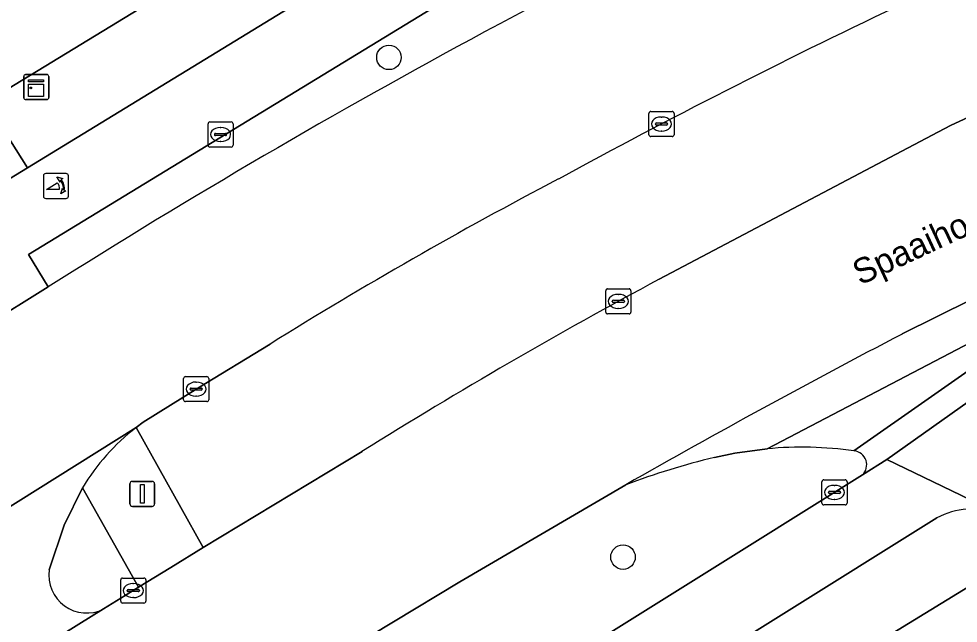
# Model space of a CAD drawing. Extents: x 157767 to 159172, y 387839 to 389425.
# Drawn here: x 158339.4 to 158376.88, y 388295.54 to 388319.67 of the extents above; entities that cross this region are included whole.
import ezdxf

# ---------------------------------------------------------------- set-up
doc = ezdxf.new("R2010")
doc.units = 0
for name, color, linetype in [('IMGEO_Berm_groen', 7, 'Continuous'), ('IMGEO_Boom', 7, 'Continuous'), ('IMGEO_Erf', 7, 'Continuous'), ('IMGEO_Fietspad_open', 7, 'Continuous'), ('IMGEO_Kast', 7, 'Continuous'), ('IMGEO_Kolk', 7, 'Continuous'), ('IMGEO_Lichtmast', 7, 'Continuous'), ('IMGEO_Openbare_ruimte_label', 7, 'Continuous'), ('IMGEO_Pand', 7, 'Continuous'), ('IMGEO_Poller', 7, 'Continuous'), ('IMGEO_Rijbaan_lokaal_gesloten', 7, 'Continuous'), ('IMGEO_Rijbaan_lokaal_open', 7, 'Continuous'), ('IMGEO_Verkeerseiland_groen', 7, 'Continuous'), ('IMGEO_Voetpad_open', 7, 'Continuous')]:
    doc.layers.add(name, color=color, linetype=linetype)

msp = doc.modelspace()

# ---------------------------------------------------------------- linework, layer by layer
at = {"layer": 'IMGEO_Berm_groen'}
for points in [[(158394.5, 388342.493), (158394.137, 388343.439), (158339.785, 388310.258), (158340.574, 388308.966)], [(158376.572, 388315.404), (158385.718, 388319.655), (158389.68, 388321.382)], [(158364.953, 388309.272), (158376.572, 388315.404)], [(158349.427, 388306.68), (158346.538, 388304.917), (158344.366, 388303.567), (158344.078, 388303.351), (158346.752, 388298.554), (158353.093, 388302.391)], [(158369.258, 388302.501), (158367.97, 388302.328), (158367.153, 388302.159)], [(158363.613, 388301.064), (158356.997, 388297.192), (158351.701, 388294), (158350.21, 388293.055), (158353.052, 388288.935), (158373.056, 388301.46)]]:
    msp.add_lwpolyline(points, dxfattribs=at)
for centre, radius, start, end in [((158493.534, 388065.053), 287.989, 113.73473, 118.07815), ((158493.159, 388070.67), 276.299, 115.45944, 118.59318), ((158499.201, 388057.708), 297.142, 118.37577, 122.26552), ((158445.272, 388152.814), 181.277, 117.72911, 121.91936), ((158462.626, 388127.262), 206.562, 118.21969, 122.02368), ((158370.643, 388287.3), 15.264, 82.1795, 95.2061), ((158372.664, 388301.862), 0.562, 17.8767, 84.2515), ((158374.95, 388270.684), 32.427, 103.9125, 110.4634), ((158372.668, 388301.862), 0.559, 314.0133, 18.055)]:
    msp.add_arc(centre, radius, start, end, dxfattribs=at)
at = {"layer": 'IMGEO_Boom'}
for centre in [(158354.168, 388318.127), (158363.505, 388298.176)]:
    msp.add_circle(centre, 0.489, dxfattribs=at)
at = {"layer": 'IMGEO_Erf'}
msp.add_lwpolyline([(158334.235, 388334.362), (158331.423, 388338.976), (158328.599, 388343.609), (158325.682, 388348.394), (158320.536, 388345.274), (158336.567, 388318.836), (158338.084, 388316.334), (158350.888, 388324.146), (158350.38, 388324.98), (158342.778, 388320.347), (158339.867, 388325.123), (158337.039, 388329.763)], close=True, dxfattribs=at)
at = {"layer": 'IMGEO_Fietspad_open'}
msp.add_lwpolyline([(158335.562, 388311.158), (158338.044, 388307.393), (158340.574, 388308.966), (158339.785, 388310.258), (158394.137, 388343.439), (158393.034, 388346.31), (158339.745, 388313.717)], close=True, dxfattribs=at)
for points in [[(158341.938, 388300.944), (158344.18, 388296.97), (158345.465, 388297.763), (158346.752, 388298.554), (158344.078, 388303.351)], [(158378.474, 388299.928), (158374.028, 388302.069), (158373.056, 388301.46), (158353.052, 388288.935), (158350.467, 388287.316), (158349.673, 388286.819), (158348.736, 388286.168), (158347.771, 388285.41), (158347, 388284.583)], [(158350.757, 388283.935), (158376.024, 388299.744)]]:
    msp.add_lwpolyline(points, dxfattribs=at)
for centre, radius, start, end in [((158349.546, 388296.335), 8.895, 127.9299, 148.7912), ((158377.455, 388297.089), 3.016, 70.2593, 118.3306)]:
    msp.add_arc(centre, radius, start, end, dxfattribs=at)
at = {"layer": 'IMGEO_Kast'}
for p, q in [((158339.672, 388317.442), (158340.513, 388317.442)), ((158340.513, 388317.442), (158339.672, 388317.442)), ((158339.597, 388316.517), (158339.597, 388317.358)), ((158339.597, 388317.358), (158339.597, 388316.517)), ((158340.597, 388317.367), (158340.597, 388316.526)), ((158340.597, 388316.526), (158340.597, 388317.367)), ((158340.522, 388316.442), (158339.681, 388316.442)), ((158339.681, 388316.442), (158340.522, 388316.442))]:
    msp.add_line(p, q, dxfattribs=at)
for points in [[(158339.792, 388317.232), (158340.392, 388317.232), (158340.392, 388317.147), (158339.792, 388317.147), (158339.792, 388317.232)], [(158339.792, 388317.057), (158340.392, 388317.057), (158340.392, 388316.568), (158339.792, 388316.568), (158339.792, 388317.057)]]:
    msp.add_lwpolyline(points, dxfattribs=at)
msp.add_circle((158339.876, 388316.906), 0.0377, dxfattribs=at)
for centre, start, end in [((158339.675, 388317.364), 92.4484, 184.2845), ((158339.675, 388317.364), 92.4484, 184.2845), ((158340.519, 388317.364), 2.4484, 94.2845), ((158340.519, 388317.364), 2.4484, 94.2845), ((158339.675, 388316.52), 182.4484, 274.2845), ((158339.675, 388316.52), 182.4484, 274.2845), ((158340.519, 388316.52), 272.4484, 4.2845), ((158340.519, 388316.52), 272.4484, 4.2845)]:
    msp.add_arc(centre, 0.0779, start, end, dxfattribs=at)
at = {"layer": 'IMGEO_Kolk'}
for p, q in [((158364.614, 388315.967), (158365.466, 388315.967)), ((158347.026, 388315.549), (158347.878, 388315.549)), ((158364.539, 388315.041), (158364.539, 388315.893)), ((158365.027, 388315.747), (158365.052, 388315.747)), ((158365.54, 388315.893), (158365.54, 388315.041)), ((158346.951, 388314.623), (158346.951, 388315.475)), ((158347.439, 388315.329), (158347.464, 388315.329)), ((158347.952, 388315.475), (158347.952, 388314.623)), ((158364.798, 388315.461), (158364.798, 388315.473)), ((158365.236, 388315.424), (158364.838, 388315.424)), ((158364.841, 388315.51), (158365.239, 388315.51)), ((158365.05, 388315.187), (158365.025, 388315.187)), ((158365.282, 388315.473), (158365.282, 388315.461)), ((158347.21, 388315.043), (158347.21, 388315.055)), ((158347.648, 388315.006), (158347.25, 388315.006)), ((158347.253, 388315.092), (158347.651, 388315.092)), ((158347.462, 388314.769), (158347.437, 388314.769)), ((158347.694, 388315.055), (158347.694, 388315.043)), ((158365.466, 388314.967), (158364.614, 388314.967)), ((158347.878, 388314.549), (158347.026, 388314.549)), ((158362.818, 388307.961), (158362.818, 388308.813)), ((158362.893, 388308.887), (158363.745, 388308.887)), ((158363.819, 388308.813), (158363.819, 388307.961)), ((158363.12, 388308.43), (158363.518, 388308.43)), ((158363.306, 388308.667), (158363.331, 388308.667)), ((158363.077, 388308.381), (158363.077, 388308.393)), ((158363.515, 388308.344), (158363.117, 388308.344)), ((158363.329, 388308.107), (158363.304, 388308.107)), ((158363.561, 388308.393), (158363.561, 388308.381)), ((158363.745, 388307.887), (158362.893, 388307.887)), ((158345.976, 388304.458), (158345.976, 388305.31)), ((158346.051, 388305.384), (158346.903, 388305.384)), ((158346.464, 388305.164), (158346.489, 388305.164)), ((158346.977, 388305.31), (158346.977, 388304.458)), ((158346.235, 388304.878), (158346.235, 388304.89)), ((158346.673, 388304.841), (158346.275, 388304.841)), ((158346.278, 388304.927), (158346.676, 388304.927)), ((158346.719, 388304.89), (158346.719, 388304.878)), ((158346.903, 388304.384), (158346.051, 388304.384)), ((158346.487, 388304.604), (158346.462, 388304.604)), ((158371.44, 388300.335), (158371.44, 388301.187)), ((158371.515, 388301.261), (158372.367, 388301.261)), ((158371.928, 388301.041), (158371.953, 388301.041)), ((158372.441, 388301.187), (158372.441, 388300.335)), ((158371.699, 388300.755), (158371.699, 388300.767)), ((158372.137, 388300.718), (158371.739, 388300.718)), ((158371.742, 388300.804), (158372.14, 388300.804)), ((158372.183, 388300.767), (158372.183, 388300.755)), ((158372.367, 388300.261), (158371.515, 388300.261)), ((158371.951, 388300.481), (158371.926, 388300.481)), ((158343.468, 388296.415), (158343.468, 388297.267)), ((158343.543, 388297.341), (158344.395, 388297.341)), ((158344.469, 388297.267), (158344.469, 388296.415)), ((158343.727, 388296.835), (158343.727, 388296.847)), ((158344.165, 388296.798), (158343.767, 388296.798)), ((158343.77, 388296.884), (158344.168, 388296.884)), ((158343.956, 388297.121), (158343.981, 388297.121)), ((158344.211, 388296.847), (158344.211, 388296.835)), ((158343.979, 388296.561), (158343.954, 388296.561)), ((158344.395, 388296.341), (158343.543, 388296.341))]:
    msp.add_line(p, q, dxfattribs=at)
for points in [[(158364.614, 388315.967), (158365.466, 388315.967)], [(158347.026, 388315.549), (158347.878, 388315.549)], [(158364.539, 388315.041), (158364.539, 388315.893)], [(158365.54, 388315.893), (158365.54, 388315.041)], [(158346.951, 388314.623), (158346.951, 388315.475)], [(158347.952, 388315.475), (158347.952, 388314.623)], [(158365.466, 388314.967), (158364.614, 388314.967)], [(158347.878, 388314.549), (158347.026, 388314.549)], [(158362.818, 388307.961), (158362.818, 388308.813)], [(158362.893, 388308.887), (158363.745, 388308.887)], [(158363.819, 388308.813), (158363.819, 388307.961)], [(158363.745, 388307.887), (158362.893, 388307.887)], [(158345.976, 388304.458), (158345.976, 388305.31)], [(158346.051, 388305.384), (158346.903, 388305.384)], [(158346.977, 388305.31), (158346.977, 388304.458)], [(158346.903, 388304.384), (158346.051, 388304.384)], [(158371.44, 388300.335), (158371.44, 388301.187)], [(158371.515, 388301.261), (158372.367, 388301.261)], [(158372.441, 388301.187), (158372.441, 388300.335)], [(158372.367, 388300.261), (158371.515, 388300.261)], [(158343.468, 388296.415), (158343.468, 388297.267)], [(158343.543, 388297.341), (158344.395, 388297.341)], [(158344.469, 388297.267), (158344.469, 388296.415)], [(158344.395, 388296.341), (158343.543, 388296.341)]]:
    msp.add_lwpolyline(points, dxfattribs=at)
for centre, radius, start, end in [((158364.616, 388315.891), 0.0765, 91.552, 178.448), ((158364.616, 388315.891), 0.0765, 91.552, 178.448), ((158365.464, 388315.891), 0.0765, 1.552, 88.448), ((158365.464, 388315.891), 0.0765, 1.552, 88.448), ((158347.028, 388315.473), 0.0765, 91.552, 178.448), ((158347.028, 388315.473), 0.0765, 91.552, 178.448), ((158347.876, 388315.473), 0.0765, 1.552, 88.448), ((158347.876, 388315.473), 0.0765, 1.552, 88.448), ((158364.838, 388315.47), 0.0403, 85.8775, 175.7526), ((158364.835, 388315.46), 0.0366, 178.938, 274.7102), ((158365.239, 388315.467), 0.043, 264.8664, 352.4533), ((158365.243, 388315.472), 0.0386, 1.7309, 96.639), ((158347.25, 388315.052), 0.0403, 85.8775, 175.7526), ((158347.247, 388315.042), 0.0366, 178.938, 274.7102), ((158347.651, 388315.049), 0.043, 264.8664, 352.4533), ((158347.655, 388315.054), 0.0386, 1.7309, 96.639), ((158364.616, 388315.043), 0.0765, 181.552, 268.448), ((158364.616, 388315.043), 0.0765, 181.552, 268.448), ((158365.464, 388315.043), 0.0765, 271.552, 358.448), ((158365.464, 388315.043), 0.0765, 271.552, 358.448), ((158347.028, 388314.625), 0.0765, 181.552, 268.448), ((158347.028, 388314.625), 0.0765, 181.552, 268.448), ((158347.876, 388314.625), 0.0765, 271.552, 358.448), ((158347.876, 388314.625), 0.0765, 271.552, 358.448), ((158362.895, 388308.811), 0.0765, 91.552, 178.448), ((158362.895, 388308.811), 0.0765, 91.552, 178.448), ((158363.743, 388308.811), 0.0765, 1.552, 88.448), ((158363.743, 388308.811), 0.0765, 1.552, 88.448), ((158363.117, 388308.39), 0.0403, 85.8775, 175.7526), ((158363.522, 388308.392), 0.0386, 1.7309, 96.639), ((158363.114, 388308.38), 0.0366, 178.938, 274.7102), ((158363.518, 388308.387), 0.043, 264.8664, 352.4533), ((158362.895, 388307.963), 0.0765, 181.552, 268.448), ((158362.895, 388307.963), 0.0765, 181.552, 268.448), ((158363.743, 388307.963), 0.0765, 271.552, 358.448), ((158363.743, 388307.963), 0.0765, 271.552, 358.448), ((158346.053, 388305.308), 0.0765, 91.552, 178.448), ((158346.053, 388305.308), 0.0765, 91.552, 178.448), ((158346.901, 388305.308), 0.0765, 1.552, 88.448), ((158346.901, 388305.308), 0.0765, 1.552, 88.448), ((158346.275, 388304.887), 0.0403, 85.8775, 175.7526), ((158346.272, 388304.877), 0.0366, 178.938, 274.7102), ((158346.676, 388304.884), 0.043, 264.8664, 352.4533), ((158346.68, 388304.889), 0.0386, 1.7309, 96.639), ((158346.053, 388304.46), 0.0765, 181.552, 268.448), ((158346.053, 388304.46), 0.0765, 181.552, 268.448), ((158346.901, 388304.46), 0.0765, 271.552, 358.448), ((158346.901, 388304.46), 0.0765, 271.552, 358.448), ((158371.517, 388301.185), 0.0765, 91.552, 178.448), ((158371.517, 388301.185), 0.0765, 91.552, 178.448), ((158372.365, 388301.185), 0.0765, 1.552, 88.448), ((158372.365, 388301.185), 0.0765, 1.552, 88.448), ((158371.739, 388300.764), 0.0403, 85.8775, 175.7526), ((158371.736, 388300.754), 0.0366, 178.938, 274.7102), ((158372.14, 388300.761), 0.043, 264.8664, 352.4533), ((158372.144, 388300.766), 0.0386, 1.7309, 96.639), ((158371.517, 388300.337), 0.0765, 181.552, 268.448), ((158371.517, 388300.337), 0.0765, 181.552, 268.448), ((158372.365, 388300.337), 0.0765, 271.552, 358.448), ((158372.365, 388300.337), 0.0765, 271.552, 358.448), ((158343.545, 388297.265), 0.0765, 91.552, 178.448), ((158343.545, 388297.265), 0.0765, 91.552, 178.448), ((158344.393, 388297.265), 0.0765, 1.552, 88.448), ((158344.393, 388297.265), 0.0765, 1.552, 88.448), ((158343.767, 388296.844), 0.0403, 85.8775, 175.7526), ((158343.764, 388296.834), 0.0366, 178.938, 274.7102), ((158344.168, 388296.841), 0.043, 264.8664, 352.4533), ((158344.172, 388296.846), 0.0386, 1.7309, 96.639), ((158343.545, 388296.417), 0.0765, 181.552, 268.448), ((158343.545, 388296.417), 0.0765, 181.552, 268.448), ((158344.393, 388296.417), 0.0765, 271.552, 358.448), ((158344.393, 388296.417), 0.0765, 271.552, 358.448)]:
    msp.add_arc(centre, radius, start, end, dxfattribs=at)
for centre, major_axis, ratio, start_param, end_param in [((158365.026, 388315.467), (-0.387, 0.002), 0.722429, 4.712389, 7.853982), ((158365.051, 388315.467), (-0.39, 0.002), 0.717154, 1.570796, 4.712389), ((158347.438, 388315.049), (-0.387, 0.002), 0.722429, 4.712389, 7.853982), ((158347.463, 388315.049), (-0.39, 0.002), 0.717154, 1.570796, 4.712389), ((158363.305, 388308.387), (-0.387, 0.002), 0.722429, 4.712389, 7.853982), ((158363.33, 388308.387), (-0.39, 0.002), 0.717154, 1.570796, 4.712389), ((158346.463, 388304.884), (-0.387, 0.002), 0.722429, 4.712389, 7.853982), ((158346.488, 388304.884), (-0.39, 0.002), 0.717154, 1.570796, 4.712389), ((158371.927, 388300.761), (-0.387, 0.002), 0.722429, 4.712389, 7.853982), ((158371.952, 388300.761), (-0.39, 0.002), 0.717154, 1.570796, 4.712389), ((158343.955, 388296.841), (-0.387, 0.002), 0.722429, 4.712389, 7.853982), ((158343.98, 388296.841), (-0.39, 0.002), 0.717154, 1.570796, 4.712389)]:
    msp.add_ellipse(centre, major_axis=major_axis, ratio=ratio, start_param=start_param, end_param=end_param, dxfattribs=at)
at = {"layer": 'IMGEO_Lichtmast'}
for p, q in [((158343.831, 388300.301), (158343.831, 388301.101)), ((158343.831, 388301.101), (158343.831, 388300.301)), ((158343.931, 388301.201), (158344.721, 388301.201)), ((158344.721, 388301.201), (158343.931, 388301.201)), ((158344.821, 388301.101), (158344.821, 388300.301)), ((158344.821, 388300.301), (158344.821, 388301.101)), ((158344.721, 388300.201), (158343.931, 388300.201)), ((158343.931, 388300.201), (158344.721, 388300.201))]:
    msp.add_line(p, q, dxfattribs=at)
msp.add_lwpolyline([(158344.251, 388301.076), (158344.401, 388301.076), (158344.401, 388300.326), (158344.251, 388300.326), (158344.251, 388301.076)], dxfattribs=at)
for centre, start, end in [((158343.931, 388301.101), 90, 180), ((158343.931, 388301.101), 90, 180), ((158344.721, 388301.101), 0, 90), ((158344.721, 388301.101), 360, 90), ((158343.931, 388300.301), 180, 270), ((158343.931, 388300.301), 180, 270), ((158344.721, 388300.301), 270, 0), ((158344.721, 388300.301), 270, 0)]:
    msp.add_arc(centre, 0.1, start, end, dxfattribs=at)
at = {"layer": 'IMGEO_Pand'}
msp.add_lwpolyline([(158378.945, 388290.243), (158381.202, 388291.668), (158379.006, 388295.224), (158377.739, 388297.275), (158374.241, 388295.13), (158377.725, 388289.49)], close=True, dxfattribs=at)
at = {"layer": 'IMGEO_Poller'}
for p, q in [((158340.383, 388313.397), (158340.383, 388312.59)), ((158340.383, 388313.397), (158340.383, 388312.59)), ((158341.285, 388313.492), (158340.477, 388313.492)), ((158341.285, 388313.492), (158340.477, 388313.492)), ((158341.379, 388312.59), (158341.379, 388313.397)), ((158341.379, 388312.59), (158341.379, 388313.397)), ((158340.477, 388312.495), (158341.285, 388312.495)), ((158340.477, 388312.495), (158341.285, 388312.495))]:
    msp.add_line(p, q, dxfattribs=at)
for points in [[(158341.062, 388313.221), (158341.05, 388313.148), (158340.925, 388313.353)], [(158340.925, 388313.353), (158341.156, 388313.287), (158341.085, 388313.255)], [(158341.018, 388312.848), (158340.505, 388312.848), (158340.935, 388313.123)], [(158341.078, 388312.676), (158341.144, 388312.907), (158341.174, 388312.839)], [(158341.21, 388312.812), (158341.282, 388312.801), (158341.078, 388312.676)]]:
    msp.add_lwpolyline(points, dxfattribs=at)
for centre, radius, start, end in [((158340.477, 388313.397), 0.0946, 90, 180), ((158340.477, 388313.397), 0.0946, 90, 180), ((158341.285, 388313.397), 0.0946, 0, 90), ((158341.285, 388313.397), 0.0946, 0, 90), ((158340.69, 388312.898), 0.332, 351.3247, 42.4854), ((158340.704, 388312.908), 0.476, 351.7527, 41.1691), ((158340.704, 388312.908), 0.516, 349.3569, 42.2912), ((158340.477, 388312.59), 0.0946, 180, 270), ((158340.477, 388312.59), 0.0946, 180, 270), ((158341.285, 388312.59), 0.0946, 270, 0), ((158341.285, 388312.59), 0.0946, 270, 0)]:
    msp.add_arc(centre, radius, start, end, dxfattribs=at)
at = {"layer": 'IMGEO_Rijbaan_lokaal_gesloten'}
for points in [[(158389.68, 388321.382), (158385.718, 388319.655), (158376.572, 388315.404), (158364.953, 388309.272)], [(158340.574, 388308.966), (158338.044, 388307.393), (158335.487, 388305.815), (158329.232, 388301.865), (158325.841, 388299.724), (158323.243, 388298.097), (158319.303, 388295.635), (158318.479, 388295.12), (158316.732, 388294.034), (158307.259, 388288.147), (158296.76, 388281.603), (158293.929, 388279.825), (158284.109, 388273.656), (158271.906, 388265.997), (158262.426, 388260.118), (158253.604, 388254.566), (158246.245, 388250), (158242.941, 388247.95), (158240.03, 388246.171), (158235.601, 388243.333), (158222.599, 388235.192), (158221.83, 388234.711)], [(158374.642, 388307.084), (158377.408, 388308.456)], [(158214.777, 388233.188), (158219.655, 388225.675), (158221.791, 388227.034), (158222.686, 388227.604), (158225.956, 388229.686), (158228.439, 388231.238), (158233.827, 388234.591), (158241.948, 388239.696), (158252.21, 388246.033), (158253.486, 388246.832), (158258.547, 388250), (158260.49, 388251.216), (158270.632, 388257.554), (158279.411, 388263.075), (158289.832, 388269.56), (158301.132, 388276.553), (158311.051, 388282.809), (158318.918, 388287.723), (158320.427, 388288.517), (158344.078, 388303.351), (158344.366, 388303.567), (158346.538, 388304.917), (158349.427, 388306.68)], [(158353.093, 388302.391), (158346.752, 388298.554), (158345.465, 388297.763), (158344.18, 388296.97), (158343.644, 388296.638), (158342.783, 388296.105), (158327.545, 388286.639)], [(158232.504, 388219.327), (158234.236, 388220.596), (158248.555, 388229.66), (158264.594, 388239.709), (158277.869, 388247.946), (158281.167, 388250), (158281.369, 388250.126), (158282.323, 388250.72), (158291.553, 388256.471), (158304.666, 388264.637), (158318.32, 388273.151), (158327.166, 388278.678), (158329.789, 388280.317), (158345.174, 388289.863), (158347.634, 388291.422), (158350.21, 388293.055), (158351.701, 388294), (158356.997, 388297.192), (158363.613, 388301.064)]]:
    msp.add_lwpolyline(points, dxfattribs=at)
for centre, radius, start, end in [((158493.534, 388065.053), 287.989, 113.73473, 118.07815), ((158493.159, 388070.67), 276.299, 115.45944, 118.59318), ((158499.201, 388057.708), 297.142, 118.37577, 122.26552), ((158445.272, 388152.814), 181.277, 117.72911, 121.91936), ((158462.626, 388127.262), 206.562, 118.21969, 122.02368), ((158532.3, 388005.133), 340.632, 117.5704, 119.684)]:
    msp.add_arc(centre, radius, start, end, dxfattribs=at)
at = {"layer": 'IMGEO_Rijbaan_lokaal_open'}
for points in [[(158433.954, 388328.707), (158424.472, 388324.867), (158422.516, 388324.075), (158421.237, 388323.557), (158419.459, 388322.798), (158415.604, 388321.154), (158404.108, 388316.461), (158396.364, 388313.266), (158393.834, 388312.24), (158393.136, 388311.957), (158381.944, 388307.393), (158380.927, 388306.975), (158374.028, 388302.069), (158378.474, 388299.928), (158380.421, 388298.991), (158386.453, 388302.761), (158424.712, 388318.46), (158427.533, 388319.501), (158491.882, 388345.812)], [(158329.827, 388307.397), (158329.58, 388307.813), (158334.451, 388310.816), (158335.188, 388311.069), (158335.562, 388311.158), (158339.745, 388313.717), (158338.084, 388316.334), (158336.567, 388318.836), (158331.773, 388315.892), (158326.649, 388312.756), (158302.653, 388298.156), (158305.681, 388293.117), (158314.034, 388298.249), (158316.619, 388299.808), (158319.186, 388301.356)], [(158344.078, 388303.351), (158320.427, 388288.517), (158322.14, 388288.992), (158323.568, 388289.196)], [(158340.619, 388297.671), (158341.213, 388299.448), (158341.938, 388300.944)], [(158327.545, 388286.639), (158342.783, 388296.105)]]:
    msp.add_lwpolyline(points, dxfattribs=at)
for centre, radius, start, end in [((158349.546, 388296.335), 8.895, 127.9299, 148.7912), ((158342.105, 388297.447), 1.503, 171.4167, 296.7998)]:
    msp.add_arc(centre, radius, start, end, dxfattribs=at)
at = {"layer": 'IMGEO_Verkeerseiland_groen'}
for points in [[(158341.938, 388300.944), (158341.213, 388299.448), (158340.619, 388297.671)], [(158342.783, 388296.105), (158343.644, 388296.638), (158344.18, 388296.97), (158341.938, 388300.944)]]:
    msp.add_lwpolyline(points, dxfattribs=at)
msp.add_arc((158342.105, 388297.447), 1.503, 171.4167, 296.7998, dxfattribs=at)
at = {"layer": 'IMGEO_Voetpad_open'}
msp.add_lwpolyline([(158393.034, 388346.31), (158392.115, 388348.703), (158387.771, 388346.651), (158377.558, 388340.419), (158368.226, 388334.726), (158362.339, 388331.133), (158353.847, 388325.951), (158350.888, 388324.146), (158338.084, 388316.334), (158339.745, 388313.717)], close=True, dxfattribs=at)
for points in [[(158377.408, 388308.456), (158374.642, 388307.084)], [(158367.153, 388302.159), (158367.97, 388302.328), (158369.258, 388302.501), (158377.986, 388307.068), (158377.52, 388307.345)], [(158372.72, 388302.422), (158378.916, 388306.759), (158377.986, 388307.068), (158369.258, 388302.501)], [(158373.056, 388301.46), (158374.028, 388302.069), (158380.927, 388306.975)], [(158379.025, 388306.741), (158378.916, 388306.759), (158372.72, 388302.422)], [(158363.283, 388288.308), (158365.475, 388289.674), (158374.241, 388295.13), (158377.739, 388297.275), (158380.421, 388298.991), (158378.474, 388299.928)], [(158376.024, 388299.744), (158350.757, 388283.935)]]:
    msp.add_lwpolyline(points, dxfattribs=at)
for centre, radius, start, end in [((158532.3, 388005.133), 340.632, 117.5704, 119.684), ((158370.643, 388287.3), 15.264, 82.1795, 95.2061), ((158372.664, 388301.862), 0.562, 17.8767, 84.2515), ((158374.95, 388270.684), 32.427, 103.9125, 110.4634), ((158372.668, 388301.862), 0.559, 314.0133, 18.055), ((158377.455, 388297.089), 3.016, 70.2593, 118.3306)]:
    msp.add_arc(centre, radius, start, end, dxfattribs=at)

# ---------------------------------------------------------------- texts
at = {"layer": 'IMGEO_Openbare_ruimte_label'}
msp.add_text('Spaaihoefweg', height=1, rotation=24.9512, dxfattribs=at).set_placement((158372.964, 388309.014))

doc.saveas('drawing.dxf')
